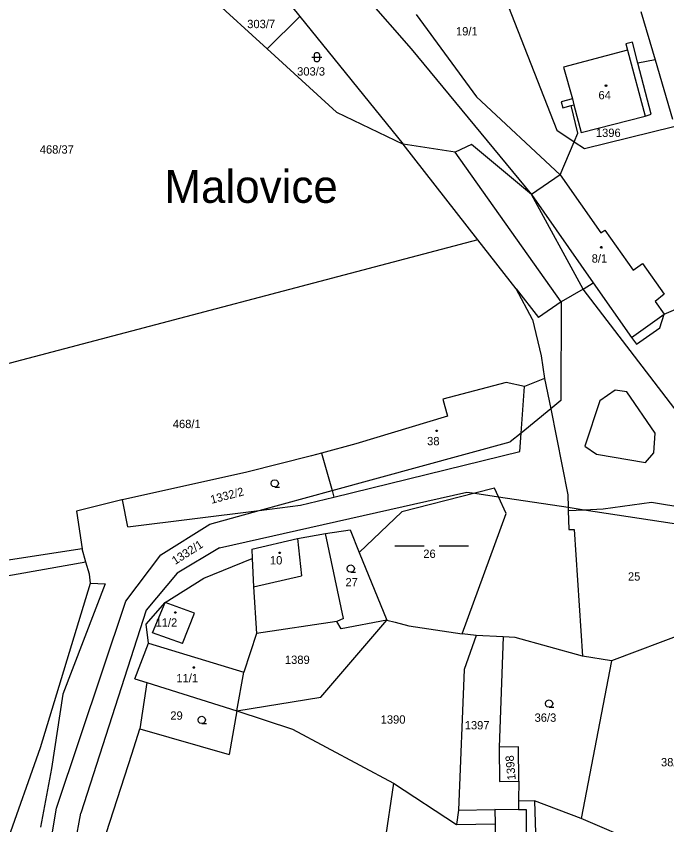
# Model space of a CAD drawing. Extents: x -852001 to -842497, y -1063614 to -1052182.
# Drawn here: x -844674.2 to -844541.5, y -1061526.1 to -1061361.2 of the extents above; entities that cross this region are included whole.
import ezdxf

# ---------------------------------------------------------------- set-up
doc = ezdxf.new("R2010")
doc.units = 0
for name, color, linetype in [('Default', 7, 'Continuous'), ('KN_HRANICE', 7, 'Continuous'), ('KN_KULTURY', 7, 'Continuous'), ('KN_PARCELY', 7, 'Continuous'), ('KN_SLUCKY', 7, 'Continuous')]:
    doc.layers.add(name, color=color, linetype=linetype)

# ---------------------------------------------------------------- blocks, each defined once
blk = doc.blocks.new('304')
at = {"layer": 'Default'}
blk.add_lwpolyline([(0, 0), (-0.38, 0.1), (-0.65, 0.37), (-0.75, 0.74), (-0.65, 1.11), (-0.38, 1.38), (-0.01, 1.48), (0.36, 1.38), (0.63, 1.11), (0.73, 0.73), (0.63, 0.35), (0.36, 0.08), (-0.02, -0.02), (0.98, -0.02)], dxfattribs=at)
blk = doc.blocks.new('316')
at = {"layer": 'Default'}
for points in [[(-0.5, 1.5), (-0.4, 1.79), (-0.15, 1.97), (0.16, 1.97), (0.41, 1.79), (0.51, 1.5), (0.51, 0.5), (0.41, 0.21), (0.16, 0.03), (-0.15, 0.03), (-0.4, 0.21), (-0.5, 0.5), (-0.5, 1.5)], [(-1, 1), (0.27, 1), (1, 1)]]:
    blk.add_lwpolyline(points, dxfattribs=at)
blk = doc.blocks.new('NAHRADNI_SYMBOL')
at = {"layer": 'Default'}
blk.add_lwpolyline([(0.09, 0.15), (0.18, 0), (0.09, -0.15), (-0.09, -0.15), (-0.18, 0), (-0.09, 0.15), (0.09, 0.15)], dxfattribs=at)
blk = doc.blocks.new('803')
at = {"layer": 'Default'}
for p, q in [((-7.5, 0), (-1.5, 0)), ((1.5, 0), (7.5, 0))]:
    blk.add_line(p, q, dxfattribs=at)
blk = doc.blocks.new('402')
at = {"layer": 'Default'}
blk.add_lwpolyline([(0.09, 0.15), (0.18, 0), (0.09, -0.15), (-0.09, -0.15), (-0.18, 0), (-0.09, 0.15), (0.09, 0.15)], dxfattribs=at)

msp = doc.modelspace()

# ---------------------------------------------------------------- linework, layer by layer
at = {"layer": 'KN_HRANICE'}
for p, q in [((-844584.6, -1061331.79), (-844563.96, -1061384.43)), ((-844628.4, -1061346.39), (-844616.36, -1061361.27)), ((-844623.03, -1061367.82), (-844636.31, -1061355.71)), ((-844604.71, -1061355.25), (-844593.67, -1061367.85)), ((-844546.85, -1061360.21), (-844543.93, -1061370.06)), ((-844616.36, -1061361.27), (-844623.03, -1061367.82)), ((-844616.36, -1061361.27), (-844595.28, -1061387.31)), ((-844592.68, -1061360.84), (-844580.38, -1061377.63)), ((-844548.55, -1061366.46), (-844549.86, -1061366.8)), ((-844549.86, -1061366.8), (-844549.56, -1061368.12)), ((-844547.43, -1061370.75), (-844548.55, -1061366.46)), ((-844608.89, -1061380.73), (-844623.03, -1061367.82)), ((-844593.67, -1061367.85), (-844569.16, -1061397.58)), ((-844549.56, -1061368.12), (-844562.59, -1061371.56)), ((-844543.93, -1061370.06), (-844547.43, -1061370.75)), ((-844543.93, -1061370.06), (-844540.35, -1061382.16)), ((-844562.59, -1061371.56), (-844560.8, -1061378.03)), ((-844544.69, -1061381.19), (-844547.43, -1061370.75)), ((-844580.38, -1061377.63), (-844563.31, -1061393.54)), ((-844560.8, -1061378.03), (-844563.09, -1061378.63)), ((-844563.09, -1061378.63), (-844562.74, -1061379.91)), ((-844562.74, -1061379.91), (-844561.01, -1061379.42)), ((-844561.01, -1061379.42), (-844560.49, -1061379.3)), ((-844559.66, -1061385.06), (-844561.01, -1061379.42)), ((-844560.49, -1061379.3), (-844558.97, -1061384.88)), ((-844608.89, -1061380.73), (-844595.28, -1061387.31)), ((-844558.97, -1061384.88), (-844545.97, -1061381.6)), ((-844545.97, -1061381.6), (-844544.69, -1061381.19)), ((-844558.34, -1061388.2), (-844540.07, -1061383.72)), ((-844563.96, -1061384.43), (-844560.41, -1061386.81)), ((-844560.41, -1061386.81), (-844559.66, -1061385.06)), ((-844563.31, -1061393.54), (-844560.41, -1061386.81)), ((-844560.41, -1061386.81), (-844558.34, -1061388.2)), ((-844580.08, -1061406.78), (-844595.28, -1061387.31)), ((-844563.31, -1061393.54), (-844569.16, -1061397.58)), ((-844569.16, -1061397.58), (-844556.53, -1061415.56)), ((-844580.08, -1061406.78), (-844717.62, -1061443.09)), ((-844572.25, -1061416.81), (-844580.08, -1061406.78)), ((-844572.25, -1061416.81), (-844567.71, -1061422.67)), ((-844568.91, -1061423.05), (-844572.25, -1061416.81)), ((-844558.62, -1061416.89), (-844563.06, -1061419.45)), ((-844558.62, -1061416.89), (-844556.53, -1061415.56)), ((-844556.53, -1061415.56), (-844548.71, -1061426.69)), ((-844563.06, -1061419.45), (-844567.71, -1061422.67)), ((-844542.06, -1061421.97), (-844537.66, -1061420.06)), ((-844568.91, -1061423.05), (-844567.19, -1061430.48)), ((-844542.99, -1061424.72), (-844542.06, -1061421.97)), ((-844547.73, -1061428.08), (-844542.99, -1061424.72)), ((-844548.71, -1061426.69), (-844547.73, -1061428.08)), ((-844567.19, -1061430.48), (-844566.46, -1061435.08)), ((-844574.31, -1061435.87), (-844587.2, -1061439.3)), ((-844570.56, -1061436.72), (-844574.31, -1061435.87)), ((-844566.46, -1061435.08), (-844570.56, -1061436.72)), ((-844566.46, -1061435.08), (-844565.22, -1061441.3)), ((-844571.24, -1061446.2), (-844570.56, -1061436.72)), ((-844587.2, -1061439.3), (-844586.28, -1061442.8)), ((-844565.22, -1061441.3), (-844561.73, -1061458.84)), ((-844586.28, -1061442.8), (-844604.97, -1061448.44)), ((-844571.51, -1061450), (-844571.24, -1061446.2)), ((-844604.97, -1061448.44), (-844611.96, -1061450.29)), ((-844613.99, -1061450.83), (-844627.22, -1061454.2)), ((-844611.96, -1061450.29), (-844613.99, -1061450.83)), ((-844611.96, -1061450.29), (-844609.8, -1061457.94)), ((-844609.42, -1061459.29), (-844571.51, -1061450)), ((-844627.22, -1061454.2), (-844652.53, -1061459.81)), ((-844609.8, -1061457.94), (-844609.42, -1061459.29)), ((-844576.68, -1061457.48), (-844580.69, -1061458.5)), ((-844575.87, -1061459.23), (-844576.68, -1061457.48)), ((-844616.21, -1061460.95), (-844609.42, -1061459.29)), ((-844580.69, -1061458.5), (-844595.6, -1061462.3)), ((-844574.27, -1061462.65), (-844575.87, -1061459.23)), ((-844561.73, -1061458.84), (-844561.68, -1061461.36)), ((-844652.69, -1061459.85), (-844661.9, -1061462.12)), ((-844652.53, -1061459.81), (-844652.69, -1061459.85)), ((-844651.48, -1061465.37), (-844652.53, -1061459.81)), ((-844624.68, -1061462.01), (-844616.21, -1061460.95)), ((-844561.68, -1061461.36), (-844561.67, -1061462)), ((-844554.5, -1061461.7), (-844544.65, -1061460.34)), ((-844544.65, -1061460.34), (-844537.49, -1061461.47)), ((-844661.9, -1061462.12), (-844660.74, -1061469.85)), ((-844651.48, -1061465.37), (-844624.68, -1061462.01)), ((-844595.6, -1061462.3), (-844604.26, -1061470.57)), ((-844583.25, -1061487.14), (-844574.27, -1061462.65)), ((-844561.67, -1061462), (-844558.37, -1061461.86)), ((-844561.67, -1061462), (-844561.52, -1061465.91)), ((-844558.37, -1061461.86), (-844554.5, -1061461.7)), ((-844611.12, -1061466.69), (-844606.12, -1061465.95)), ((-844606.12, -1061465.95), (-844604.26, -1061470.57)), ((-844561.52, -1061465.91), (-844560.4, -1061465.91)), ((-844560.4, -1061465.91), (-844558.74, -1061491.73)), ((-844626.2, -1061469.92), (-844616.87, -1061467.72)), ((-844616.87, -1061467.72), (-844611.12, -1061466.69)), ((-844607.46, -1061484.06), (-844611.12, -1061466.69)), ((-844660.74, -1061469.85), (-844687.29, -1061473.84)), ((-844660.03, -1061472.53), (-844660.74, -1061469.85)), ((-844626.2, -1061469.92), (-844626.1, -1061471.78)), ((-844604.26, -1061470.57), (-844598.62, -1061484.35)), ((-844660.03, -1061472.53), (-844690.91, -1061478.06)), ((-844659.29, -1061474.99), (-844660.03, -1061472.53)), ((-844635.96, -1061475.84), (-844626.1, -1061471.78)), ((-844626.1, -1061471.78), (-844625.8, -1061477.58)), ((-844659.07, -1061476.84), (-844659.29, -1061474.99)), ((-844643.87, -1061480.8), (-844635.96, -1061475.84)), ((-844669.25, -1061510.34), (-844659.07, -1061476.84)), ((-844656.11, -1061476.98), (-844664.72, -1061499.45)), ((-844659.07, -1061476.84), (-844656.11, -1061476.98)), ((-844625.8, -1061477.58), (-844625.23, -1061487.08)), ((-844647.74, -1061485.2), (-844643.87, -1061480.8)), ((-844646.4, -1061486.96), (-844643.87, -1061480.8)), ((-844637.85, -1061482.93), (-844643.87, -1061480.8)), ((-844640.3, -1061489.16), (-844637.85, -1061482.93)), ((-844612.11, -1061500.09), (-844598.62, -1061484.35)), ((-844607.46, -1061484.06), (-844608.86, -1061484.63)), ((-844598.62, -1061484.35), (-844607.93, -1061486.13)), ((-844598.62, -1061484.35), (-844596.96, -1061484.81)), ((-844647.22, -1061489.07), (-844647.74, -1061485.2)), ((-844608.86, -1061484.63), (-844625.23, -1061487.08)), ((-844607.93, -1061486.13), (-844608.86, -1061484.63)), ((-844596.96, -1061484.81), (-844594.13, -1061485.5)), ((-844594.13, -1061485.5), (-844583.25, -1061487.14)), ((-844533.17, -1061485.27), (-844552.79, -1061492.69)), ((-844640.3, -1061489.16), (-844646.4, -1061486.96)), ((-844625.23, -1061487.08), (-844627.77, -1061494.95)), ((-844580.39, -1061487.47), (-844583.25, -1061487.14)), ((-844580.39, -1061487.47), (-844582.89, -1061494.41)), ((-844574.94, -1061487.74), (-844580.39, -1061487.47)), ((-844574.94, -1061487.74), (-844575.71, -1061510.27)), ((-844572.44, -1061487.93), (-844574.94, -1061487.74)), ((-844650.03, -1061496.31), (-844647.22, -1061489.07)), ((-844558.74, -1061491.73), (-844572.44, -1061487.93)), ((-844552.79, -1061492.69), (-844559.01, -1061524.82)), ((-844552.79, -1061492.69), (-844558.74, -1061491.73)), ((-844582.89, -1061494.41), (-844584.01, -1061523.15)), ((-844629.2, -1061502.88), (-844627.77, -1061494.95)), ((-844650.03, -1061496.31), (-844647.56, -1061497.06)), ((-844647.56, -1061497.06), (-844649.02, -1061506.53)), ((-844647.56, -1061497.06), (-844629.2, -1061502.88)), ((-844664.72, -1061499.45), (-844667, -1061514.65)), ((-844629.2, -1061502.88), (-844612.11, -1061500.09)), ((-844629.2, -1061502.88), (-844630.81, -1061511.79)), ((-844629.2, -1061502.88), (-844617.88, -1061506.63)), ((-844650.67, -1061511.68), (-844649.02, -1061506.53)), ((-844649.02, -1061506.53), (-844630.81, -1061511.79)), ((-844617.88, -1061506.63), (-844597.26, -1061517.65)), ((-844676.11, -1061529.78), (-844669.25, -1061510.34)), ((-844571.81, -1061510.23), (-844575.71, -1061510.27)), ((-844575.71, -1061510.27), (-844575.64, -1061517.27)), ((-844571.74, -1061517.23), (-844571.81, -1061510.23)), ((-844656.75, -1061530.65), (-844650.67, -1061511.68)), ((-844667, -1061514.65), (-844669.29, -1061526.62)), ((-844575.64, -1061517.27), (-844571.74, -1061517.23)), ((-844571.74, -1061517.23), (-844571.77, -1061521.17)), ((-844597.26, -1061517.65), (-844605.93, -1061575.54)), ((-844597.26, -1061517.65), (-844584.4, -1061526.05)), ((-844571.77, -1061521.17), (-844571.79, -1061523.05)), ((-844571.77, -1061521.17), (-844568.5, -1061521.23)), ((-844568.5, -1061521.23), (-844568.15, -1061533.97)), ((-844559.01, -1061524.82), (-844568.5, -1061521.23)), ((-844584.01, -1061523.15), (-844576.61, -1061523.02)), ((-844576.61, -1061523.02), (-844576.55, -1061525.94)), ((-844571.79, -1061523.05), (-844576.61, -1061523.02)), ((-844529.43, -1061537.42), (-844559.01, -1061524.82)), ((-844584.4, -1061526.05), (-844576.55, -1061525.94)), ((-844576.55, -1061525.94), (-844576.36, -1061539.23))]:
    msp.add_line(p, q, dxfattribs=at)
at = {"layer": 'KN_SLUCKY'}
for p, q in [((-844549.56, -1061368.12), (-844545.97, -1061381.6)), ((-844560.8, -1061378.03), (-844560.49, -1061379.3)), ((-844584.67, -1061388.89), (-844595.28, -1061387.31)), ((-844581.36, -1061387.39), (-844584.67, -1061388.89)), ((-844569.16, -1061397.58), (-844581.36, -1061387.39)), ((-844563.06, -1061419.45), (-844584.67, -1061388.89)), ((-844563.31, -1061393.54), (-844554.96, -1061405.39)), ((-844558.62, -1061416.89), (-844569.16, -1061397.58)), ((-844554.96, -1061405.39), (-844554.15, -1061404.81)), ((-844554.15, -1061404.81), (-844548.39, -1061412.98)), ((-844548.39, -1061412.98), (-844546.51, -1061411.66)), ((-844546.51, -1061411.66), (-844542.07, -1061417.88)), ((-844532.72, -1061450.71), (-844558.62, -1061416.89)), ((-844542.07, -1061417.88), (-844543.9, -1061419.36)), ((-844563.06, -1061419.45), (-844563.13, -1061439.59)), ((-844543.9, -1061419.36), (-844542.06, -1061421.97)), ((-844548.71, -1061426.69), (-844542.06, -1061421.97)), ((-844552.06, -1061437.44), (-844555.2, -1061439.65)), ((-844549.68, -1061437.82), (-844552.06, -1061437.44)), ((-844543.9, -1061446.22), (-844549.68, -1061437.82)), ((-844563.13, -1061439.59), (-844565.22, -1061441.3)), ((-844555.2, -1061439.65), (-844558.26, -1061448.9)), ((-844565.22, -1061441.3), (-844571.24, -1061446.2)), ((-844571.24, -1061446.2), (-844573.45, -1061448)), ((-844544.19, -1061450.24), (-844543.9, -1061446.22)), ((-844609.8, -1061457.94), (-844573.45, -1061448)), ((-844558.26, -1061448.9), (-844555.86, -1061450.54)), ((-844555.86, -1061450.54), (-844545.86, -1061452.19)), ((-844545.86, -1061452.19), (-844544.19, -1061450.24)), ((-844624.68, -1061462.01), (-844609.8, -1061457.94)), ((-844632.78, -1061469.59), (-844582.31, -1061458.26)), ((-844582.31, -1061458.26), (-844580.69, -1061458.5)), ((-844580.69, -1061458.5), (-844575.87, -1061459.23)), ((-844575.87, -1061459.23), (-844561.68, -1061461.36)), ((-844561.68, -1061461.36), (-844558.37, -1061461.86)), ((-844634.73, -1061464.76), (-844624.68, -1061462.01)), ((-844558.37, -1061461.86), (-844538.17, -1061464.9)), ((-844644.73, -1061471.07), (-844634.73, -1061464.76)), ((-844616.87, -1061467.72), (-844616.07, -1061475.32)), ((-844632.78, -1061469.59), (-844641.42, -1061474.8)), ((-844651.89, -1061480.51), (-844644.73, -1061471.07)), ((-844641.42, -1061474.8), (-844647.72, -1061482.35)), ((-844625.8, -1061477.58), (-844616.07, -1061475.32)), ((-844665.98, -1061522.69), (-844651.89, -1061480.51)), ((-844647.72, -1061482.35), (-844661.05, -1061523.77)), ((-844647.22, -1061489.07), (-844627.77, -1061494.95)), ((-844671.44, -1061554.37), (-844665.98, -1061522.69)), ((-844666.26, -1061551.77), (-844661.05, -1061523.77)), ((-844584.01, -1061523.15), (-844584.4, -1061526.05)), ((-844570.17, -1061523.06), (-844571.79, -1061523.05)), ((-844570.1, -1061539.27), (-844570.17, -1061523.06))]:
    msp.add_line(p, q, dxfattribs=at)

# ---------------------------------------------------------------- block references
at = {"layer": 'KN_KULTURY'}
for name, p in [('316', (-844612.9, -1061370.55)), ('402', (-844553.93, -1061375.35)), ('402', (-844554.91, -1061408.33)), ('NAHRADNI_SYMBOL', (-844588.49, -1061445.75)), ('304', (-844621.49, -1061457.21)), ('803', (-844589.49, -1061469.18)), ('402', (-844620.5, -1061470.65)), ('304', (-844605.99, -1061474.59)), ('402', (-844641.79, -1061482.81)), ('402', (-844638, -1061494.04)), ('304', (-844565.54, -1061502.13)), ('304', (-844636.37, -1061505.46))]:
    msp.add_blockref(name, p, dxfattribs=at)

# ---------------------------------------------------------------- texts
at = {"layer": 'KN_PARCELY'}
for s, height, p in [('303/7', 1.7, (-844627.11, -1061363.63)), ('19/1', 1.7, (-844584.53, -1061365.11)), ('303/3', 1.7, (-844616.93, -1061373.3)), ('64', 1.7, (-844555.47, -1061378.14)), ('1396', 1.7, (-844556, -1061385.82)), ('468/37', 1.7, (-844669.42, -1061389.22)), ('Malovice', 6.7, (-844643.99, -1061399.26)), ('8/1', 1.7, (-844556.85, -1061411.45)), ('468/1', 1.7, (-844642.29, -1061445.2)), ('38', 1.7, (-844590.42, -1061448.7)), ('10', 1.7, (-844622.48, -1061473.01)), ('26', 1.7, (-844591.2, -1061471.68)), ('25', 1.7, (-844549.46, -1061476.31)), ('27', 1.7, (-844607.08, -1061477.48)), ('11/2', 1.7, (-844645.81, -1061485.71)), ('1389', 1.7, (-844619.42, -1061493.3)), ('11/1', 1.7, (-844641.56, -1061497.04)), ('29', 1.7, (-844642.79, -1061504.68)), ('1390', 1.7, (-844599.89, -1061505.48)), ('36/3', 1.7, (-844568.5, -1061505.1)), ('1397', 1.7, (-844582.75, -1061506.65)), ('38/1', 1.7, (-844542.72, -1061514.19))]:
    msp.add_text(s, height=height, dxfattribs=at).set_placement(p)
for s, rotation, p in [('1332/2', 14.725, (-844634.37, -1061460.65)), ('1332/1', 32.659, (-844641.8, -1061473.13)), ('1398', 94.996, (-844572.34, -1061516.92))]:
    msp.add_text(s, height=1.7, rotation=rotation, dxfattribs=at).set_placement(p)

doc.saveas('drawing.dxf')
